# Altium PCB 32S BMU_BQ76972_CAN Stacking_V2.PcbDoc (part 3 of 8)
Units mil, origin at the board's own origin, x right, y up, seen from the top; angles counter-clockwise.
Board outline 7319.29 x 5216.54 mil, 4 copper layers (Top Layer, Layer 1, Layer 2, Bottom Layer), stack 73.068 mil thick; 811 components, 524 nets, 2320 pads, 2669 vias.
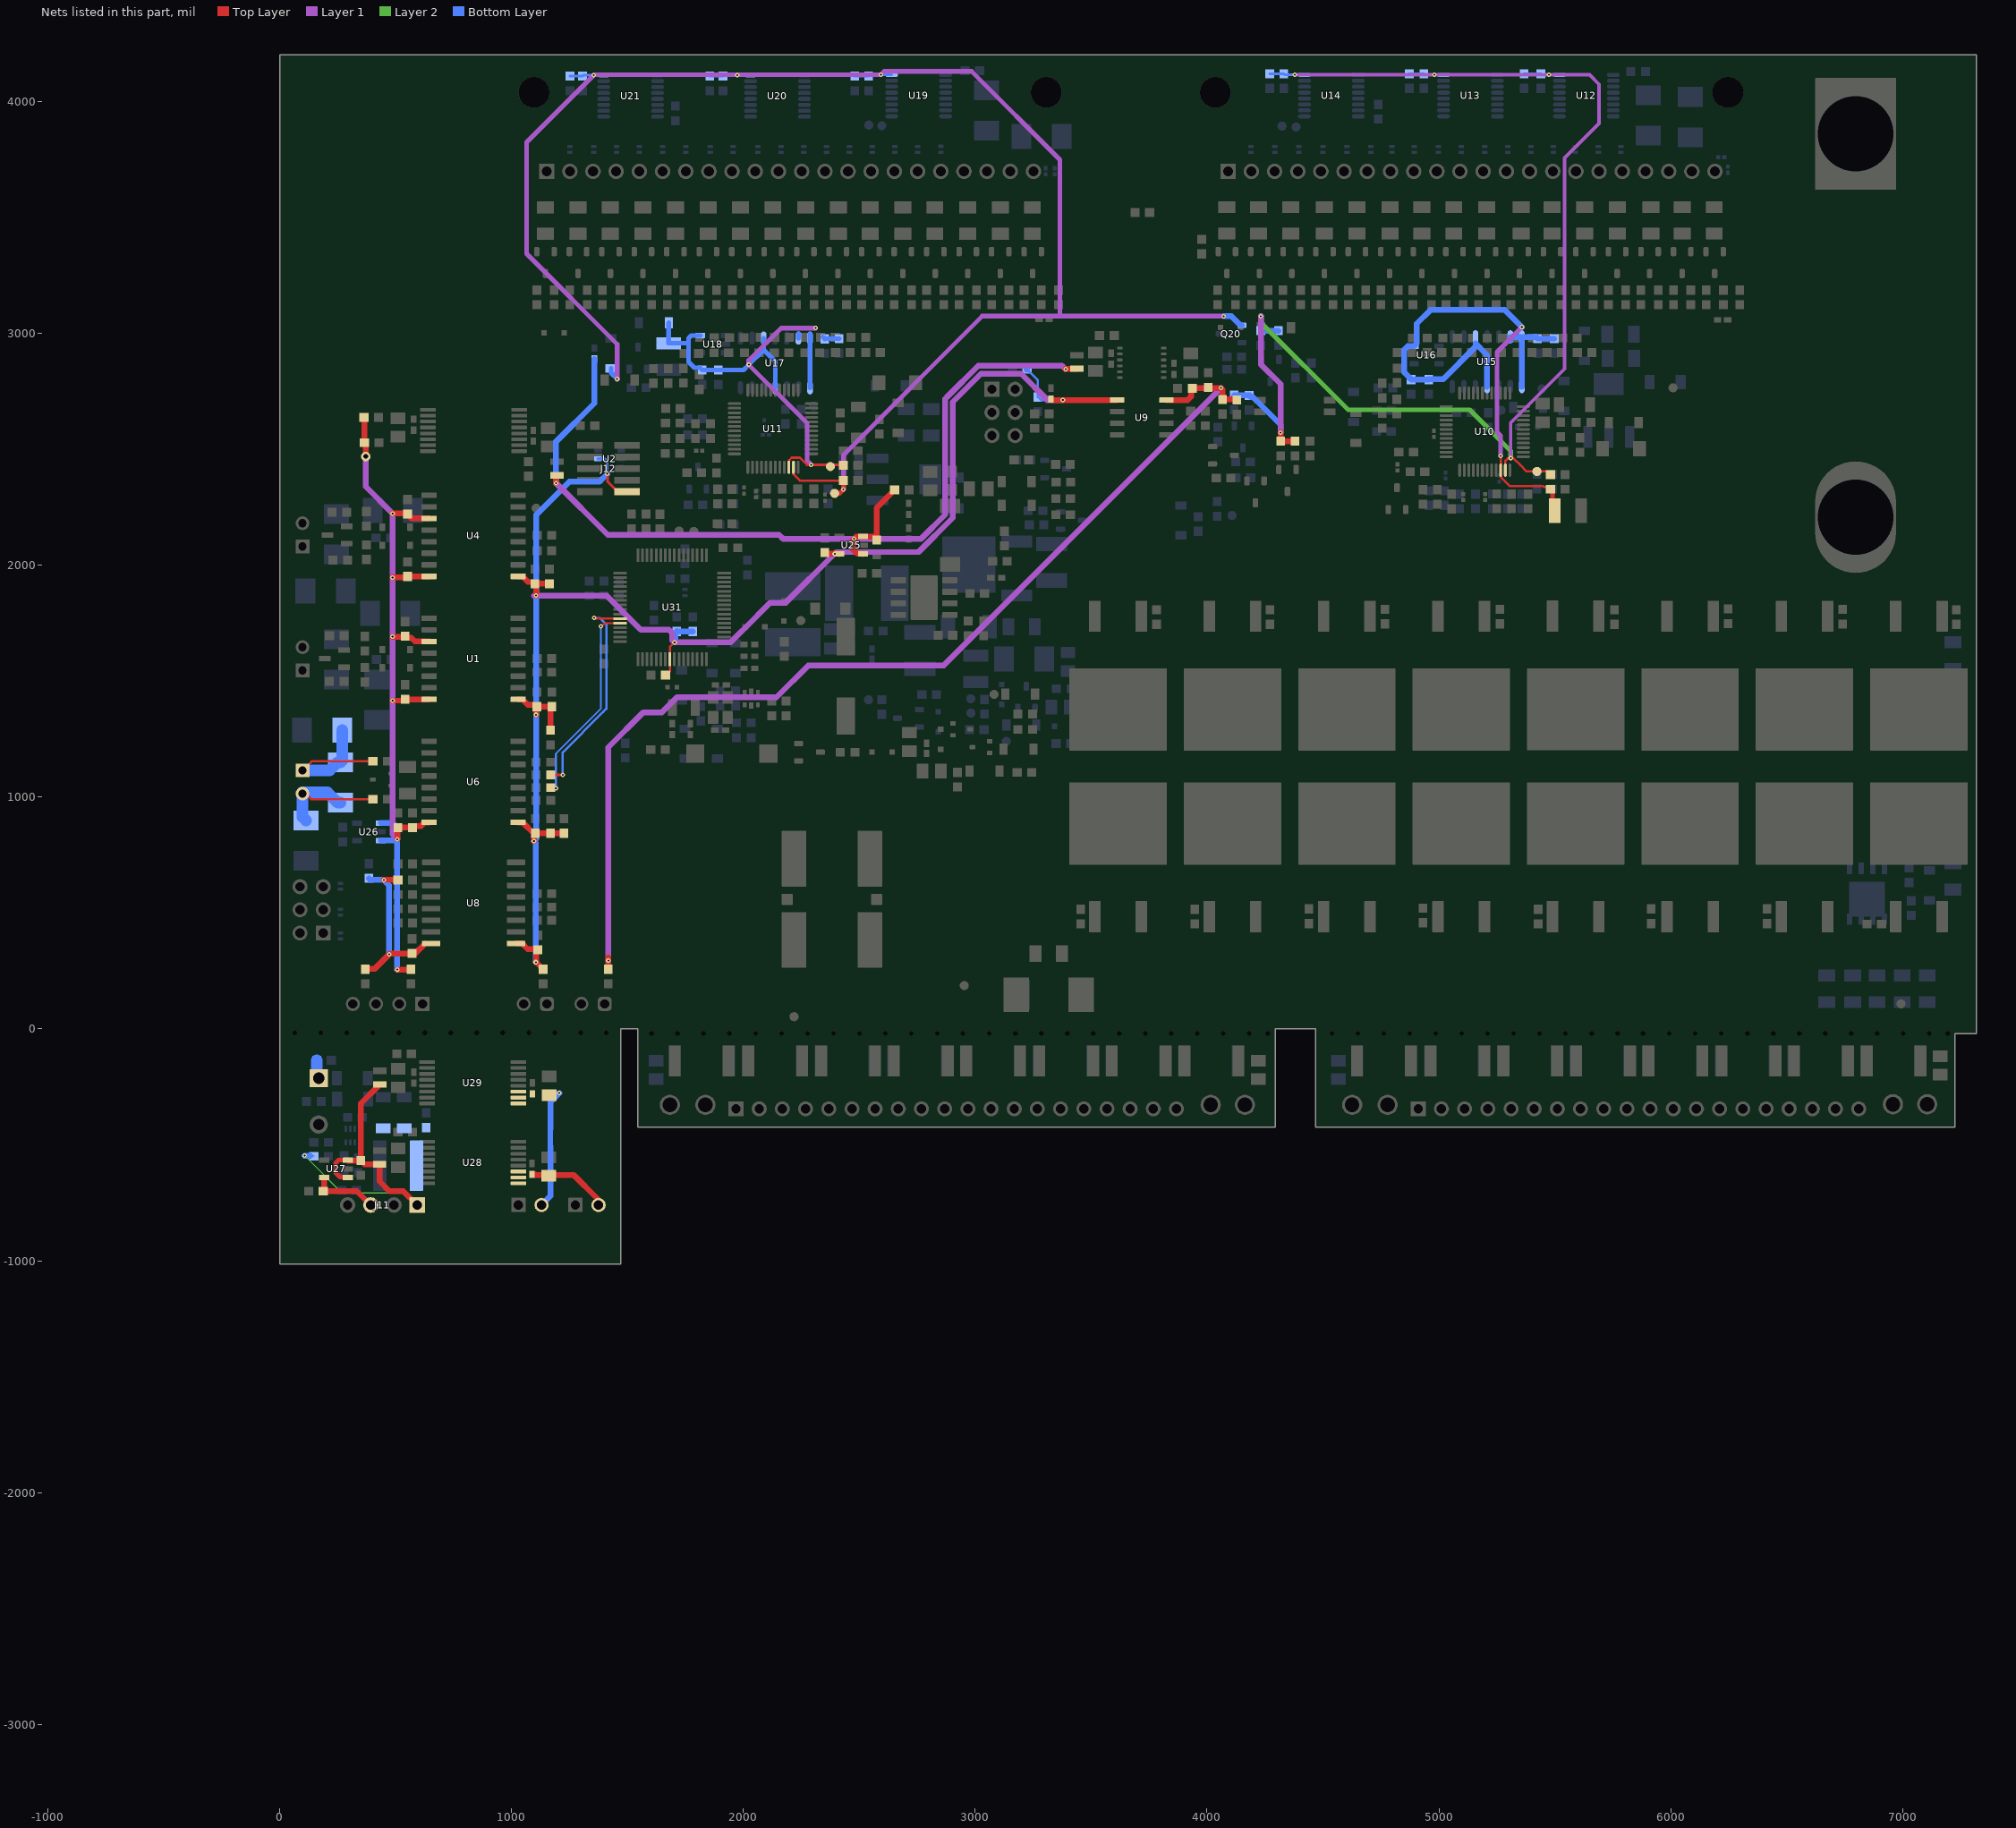
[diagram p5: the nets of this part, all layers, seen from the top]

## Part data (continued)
D38: library part CMP-0005625-1, "Diode, Zener, 91 V, 5 W, SMB", Manufacturer="Micro Commercial Components", PartNumber=SMBJ5375B-TP, Power_W=5W, Supplier Part Number 1=SMBJ5375B-TPMSTR-ND
D39: library part CMP-0076979-3, "Diode, Switching, 100 V, 0.25 A, SOD-523", Manufacturer=Nexperia, Value1=0.25A, Value2=1.25V
D40 D41: library part CMP-0080707-2, "Diode, Schottky, 20 V, 0.5 A, SOD-123", Manufacturer="Diodes Inc.", Value1=0.5A, Value2=0.33V
D43 D44 D45 D46: library part CMP-0006055-3, "Diode, TVS, Bi, 60V， SMB", Manufacturer=Bourns, Value1=600W
D48: library part CMP-0001373-1, "Diode, TVS, Bi, 120 V，3000 W,SMD (non-polarized)", Breakdown Voltage=60V, Clamping Voltage=87.1V, Digikey Part Number=SMDJ54CACT-ND, Manufacturer="Littelfuse Inc", Mouser Part Number=576-SMDJ54CA, Operating Temperature Range="-65°C to +150°C"
D49 D50 D51 D52 D53 D54 D55 D56 D57: library part CMP-0005601-2, "Diode, TVS, Bi, 7 V, SMB", Manufacturer=Littelfuse, Value1=600W
F1: library part CMP-0122193-1, "Fuse Power 150A 240V Bolt Flat 56 X 17.4 X 19.1mm", Digikey Part Number=118-PF-MB1-150-ND, Fuse Current=150A, Fuse Interrupt Dc Current=50000A, Manufacturer=Bourns, Mouser Part Number=652-PF-MB1-150, Operating Temperature Range="-55°C to +125°C"
J1 J2: library part CMP-0087165-1, "Connector Header Through Hole, Right Angle 22 position 0.100\" (2.54mm)", Current_A=3A, Manufacturer=Molex, Voltage_V=250V
J3 J4: library part CMP-0075406-2, "Header, 100mil, 3x2, Gold, TH", Color=Black, Current_A=6.3A, Manufacturer=Samtec, Supplier Part Number 1=SAM1028-03-ND, Voltage_V=550V
J5: library part CMP-0074910-1, "Terminal Block, 5.08 mm, 2x1, Brass, TH", Color=Blue, Current_A=15A, Manufacturer="On-Shore Technology", Supplier Part Number 1=ED1609-ND, Voltage_V=300V
J6 J7: library part CMP-0077643-1, "Header, 2.54mm, 2x1, Gold, TH", Color=Black, Current_A=5.7A, Manufacturer=Samtec, Supplier Part Number 1=SAM1038-02-ND, Voltage_V=550V
J8: library part CMP-0054583-1, "Header, 2.54 mm, 4x1, Gold, TH", Color=Black, Current_A=3A, Manufacturer="Sullins Connector Solutions", Supplier Part Number 1=S1011E-04-ND, Voltage_V=1.8kV
J9 J10: library part CMP-0122186-1, "2 Position Header Connector 0.100\" (2.54mm) Through Hole, Right Angle Tin", Current_A=3A, Digikey Part Number=S5438-ND, Manufacturer=Sullins, Operating Temperature Range="-40°C to +105°C", Voltage_V=250V
J11: library part CMP-0054639-1, "Receptacle, 100mil, 4x1, Gold, R/A, TH", Manufacturer="Sullins Connector Solutions", Supplier Part Number 1=S5479-ND
J12: library part CMP-0075634-1, "Header(Shrouded), 1.27mm, 5x2, Gold, SMT", Color=Black, Current_A=3.3A, Manufacturer=Samtec, Supplier Part Number 1=SAM8799-ND
J14 J15: library part CMP-0075434-1, "Header, 100mil, 20x1, Gold, TH", Color=Black, Current_A=6.3A, Manufacturer="Wurth Elektronik", Supplier Part Number 1=SAM1029-20-ND, Voltage_V=550V
L1: library part CMP-0064154-1, "Inductor, Shielded, 1 uH, 2.7 A, 0.039 ohm, SMD", Manufacturer="Wurth Elektronik", Supplier Part Number 1=732-4863-1-ND, Value1="0.039 ohm", Value2=2.7A, ValueDisplayed=1uH
L2 L5: library part CMP-0122125-1, "51 µH @ 100 kHz 2 Line Common Mode Choke Surface Mount 2.6 kOhms @ 10 MHz 200mA DCR 700mOhm", Digikey Part Number=118-SRF3225TAC-510YCT-ND, Impedance At Frequency="2600Ω @ 10MHz", Manufacturer=Bourns, Mouser Part Number=652-SRF3225TAC-510Y, Operating Temperature Range="-55°C to +150°C", Test Frequency=100kHz, Tolerance_%=-30/+50%
L3 L4 L6 L7 L8 L9: library part CMP-0003196-2, "Ferrite Bead, 600 ohm @ 100 MHz, 0.2 A, 0603", Manufacturer="Wurth Elektronik", Supplier Part Number 1=732-1583-1-ND, Value1="0.45 ohm", Value2=0.2A, ValueDisplayed="600 ohm"
L10: library part CMP-0064631-1, "Inductor, Shielded Drum Core, Metal Composite, 68 uH, 0.87 A, 0.239 ohm, SMD", Manufacturer="Wurth Elektronik", Supplier Part Number 1=732-1201-1-ND, Value1="0.239 ohm", Value2=0.87A, ValueDisplayed=68uH
L11: library part CMP-0064174-2, "Inductor, Shielded, Hyperflux, 10 µH, 5 A, 0.02915 ohm, SMD", Manufacturer="Wurth Elektronik", Supplier Part Number 1=732-10707-1-ND, Value1="0.02915 ohm", Value2=5A, ValueDisplayed=10uH
L12 L13 L14 L15: library part CMP-0100941-1, "WE-PMCI SMT Power Molded Chip Inductor, size 0805, 2.2uH, 2.1A, 190mOhm", Case/Size Code=0805, DC Resistance=180mOhm, DC Resistance Max=190mOhm, Inductance=2.2uH, Manufacturer="Wurth Elektronik", Operating Temperature Max=125°C, Operating Temperature Min=-40°C, Rated Current=2.1A, Saturation Current=2.4A, Self Resonant Frequency=45MHz
LED1: library part CMP-0074720-1, "LED, RGB, SMD", Color=RGB, Manufacturer=Everlight, Supplier Part Number 1=19-337/R6GHBHC-A01/2T-ND, Value1=W, Value2=3.8V
Logo3: library part CMP-0074847-1, "FCC_disclaimer"
Logo4: library part CMP-0074835-1, "IEC 61010-1 High Voltage Warning"
Logo5: library part CMP-0074844-1
Logo6: library part CMP-0074769-1
P1 P2 P3: "Header, 2-Pin"
Q1 Q2 Q3 Q4 Q7 Q8 Q10 Q11 Q12 Q13 Q14 Q15 Q17 Q18 Q21 Q22 Q24 Q25 Q26 Q27 Q28 Q29 Q30 Q31 Q32 Q33 Q36 Q37 Q39 Q40 Q41 Q43: library part CMP-0000433-1, "Transistor, NPN, 40 V, 0.8 A, SOT-23", Manufacturer="NXP Semiconductor", Supplier Part Number 1=568-6225-1-ND, Value1="0.8 A", Value2=300
Q5 Q6 Q16 Q19 Q66: library part CMP-0000338-1, "Transistor, PNP, 80 V, 0.5 A, SOT-23", Manufacturer="ON Semiconductor", Supplier Part Number 1=MMBTA56LT1GOSDKR-ND, Value1="0.5 A"
Q9 Q20 Q23: library part CMP-0000488-1, "Transistor, NPN, 60 V, 0.5 A, AEC-Q101, SOT-23", Manufacturer="ON Semiconductor", Supplier Part Number 1=MMBTA05LT1GOSCT-ND, Value1="0.5 A"
Q34 Q35: library part CMP-0000473-2, "Transistor, NPN, 100 V, 1 A, AEC-Q101, SOT-223", Manufacturer="Diodes Inc.", Supplier Part Number 1=FZT493CT-ND, Value1="1 A", Value2=300
Q38 Q42: library part CMP-0000487-2, "Transistor, NPN, 65 V, 0.1 A, SOT-23", Manufacturer="NXP Semiconductor", Supplier Part Number 1=568-1632-1-ND, Value1="0.1 A", Value2=450
Q44: library part CMP-0000776-1, "MOSFET, N-CH, 60 V, 0.115 A, SOT-323", Alternate Manufacturer=None, Manufacturer="Diodes Inc.", Supplier Part Number 1=2N7002W-FDICT-ND, Value1=7
Q45 Q46 Q47 Q48 Q49 Q50 Q51 Q52 Q56 Q57 Q58 Q59 Q60 Q61 Q62 Q63: library part CMP-0001086-1, "MOSFET, N-CH, 200 V, 134A, DDPAK", Alternate Manufacturer=None, Manufacturer="Infineon Technologies", Value2="70 nC"
Q53: library part CMP-0000116-2, "MOSFET, P-CH, -150 V, -3 A, PowerPAK SO-8", Alternate Manufacturer=None, Manufacturer=Vishay-Siliconix, Supplier Part Number 1=SI7439DP-T1-E3CT-ND, Value2="88 nC"
Q54: library part CMP-0000035-3, "MOSFET, P-CH, -20 V, -0.82 A, SOT-323", Alternate Manufacturer=None, Manufacturer="Diodes Inc.", Value1=0.7, Value2="0.622 nC"
Q55: library part CMP-0074710-1, "Transistor, NPN, 150 V, 1 A, AEC-Q101, SOT-23", Manufacturer="Diodes Inc.", Supplier Part Number 1=FMMT495CT-ND, Value1="1 A", Value2=300.0
Q64: library part CMP-0000093-2, "MOSFET, P-CH, -150 V, -0.53 A, SOT-23", Alternate Manufacturer=None, Manufacturer=Vishay-Siliconix, Supplier Part Number 1=SI2325DS-T1-E3CT-ND, Value2="7.7 nC"
Q65: library part CMP-0000947-2, "MOSFET, N-CH, 100 V, 0.17 A, SOT-23", Alternate Manufacturer=None, Manufacturer="Fairchild Semiconductor", Supplier Part Number 1=BSS123NCT-ND, Value1=1, Value2="1.8 nC"
Q67: library part CMP-0000504-2, "Transistor, NPN, 150 V, 1 A, AEC-Q101, DPAK", Manufacturer="Diodes Inc.", Supplier Part Number 1=ZXTN4004KTCDICT-ND, Value1="1 A"
Q68: library part CMP-0000488-2, "Transistor, NPN, 60 V, 0.5 A, AEC-Q101, SOT-23", Manufacturer="ON Semiconductor", Supplier Part Number 1=MMBTA05LT1GOSCT-ND, Value1="0.5 A"
R1 R48 R49: library part CMP-0025885-5, "RES, 0, 5%, 0.1 W, 0603", Manufacturer=Yageo, Power_W=100mW, Supplier Part Number 1=311-0.0GRCT-ND, TempCo="200 ppm/C", Tolerance_%=5%, Value2=0.1W, Value_Code=0000, ValueDisplayed=NC
R2 R152 R153: library part CMP-0025697-4, "RES, 0, 5%, 0.1 W, AEC-Q200 Grade 0, 0603", Manufacturer=Vishay-Dale, Power_W=100mW, Supplier Part Number 1=541-0.0GCT-ND, TempCo="200 ppm/C", Tolerance_%=5%, Value2=0.1W, Value_Code=0000, ValueDisplayed=0
R3: library part CMP-0122174-1, "High-Precision Low-TCR Alloy Current Sensing Resistor 0.3mOhm 1% 25ppm/°C 15W 3951", Manufacturer="C&B ELECTRONICS", Operating Temperature Range="-55°C to +170°C", Power_W=15W, TempCo=25ppm/°C, Tolerance_%=1%
R5 R28 R30 R45 R188 R189 R192 R199 R249 R252 R254 R329: library part CMP-0021998-4, "RES, 10.0 k, 1%, 0.1 W, AEC-Q200 Grade 0, 0603", Manufacturer=Vishay-Dale, Power_W=100mW, Supplier Part Number 1=541-10.0KHCT-ND, TempCo="100 ppm/C", Tolerance_%=1%, Value2=0.1W, Value_Code=10k0, ValueDisplayed=10.0k
R6 R7 R11 R12 R14 R15 R16 R18 R19 R22 R27 R31 R35 R36 R37 R38 R39 R40 R46 R47 R51 R53 R54 R91 R92 R95 R96 R99 R100 R103 R104 R107 R108 R111 R112 R115 R116 R119 R154 R157 R158 R161 R162 R165 R166 R169 R170 R173 R174 R177 R178 R181 R182 R185 R186 R198 R200 R211 R218 R239 R251 R292: library part CMP-0021991-2, "RES, 100, 1%, 0.1 W, 0603", Manufacturer=Vishay-Dale, Power_W=100mW, Supplier Part Number 1=541-100HCT-ND, TempCo="100 ppm/C", Tolerance_%=1%, Value2=0.1W, Value_Code=100R, ValueDisplayed=100
R8: library part CMP-0022438-1, "RES, 47.0 k, 1%, 0.1 W, AEC-Q200 Grade 0, 0603", Manufacturer=Vishay-Dale, Power_W=100mW, Supplier Part Number 1=541-47.0KHCT-ND, TempCo="100 ppm/C", Tolerance_%=1%, Value2=0.1W, Value_Code=47k0, ValueDisplayed=47.0k
R9 R10 R17 R20: library part CMP-0023213-5, "RES, 60.4, 1%, 0.1 W, 0603", Manufacturer=Yageo, Power_W=100mW, Supplier Part Number 1=311-60.4HRCT-ND, TempCo="100 ppm/C", Tolerance_%=1%, Value2=0.1W, Value_Code=60R4, ValueDisplayed=60.4
R13 R191 R193 R195 R197 R202 R204 R206 R208 R210 R212 R215 R217 R263 R264 R265 R266 R267 R273 R295 R296 R298 R301 R315 R318: "RES, 0, 5%, 0.063 W, 0402", Manufacturer=Vishay-Dale, Power_W=0.063, Supplier Part Number 1=541-0.0JCT-ND, TempCo="200 ppm/C", Tolerance_%=5, Value1=5%, Value2=0.063W, Value_Code=0000, ValueDisplayed=0
R21: library part CMP-0088648-1, "Res Thin Film 0402 100K Ohm 0.1% 1/16W ±25ppm/°C Molded SMD SMD Punched Carrier T/R", Digikey Part Number=P100KDCCT-ND, Manufacturer=Panasonic, Mouser Part Number=667-ERA-2AEB104X, Octopart Part Number=aea26725a1f47165, Operating Temperature Range="-55°C to +155°C", Power_W=63mW, TempCo=25ppm/°C, Tolerance_%=0.1%, Voltage=25V
R23: library part CMP-0026878-1, "RES, 220, 5%, 0.063 W, 0402", Manufacturer=Vishay-Dale, Power_W=63mW, Supplier Part Number 1=541-220JCT-ND, TempCo="200 ppm/C", Tolerance_%=5%, Value2=0.063W, Value_Code=220R, ValueDisplayed=220
R24 R25: library part CMP-0026906-1, "RES, 330, 5%, 0.063 W, 0402", Manufacturer=Vishay-Dale, Power_W=63mW, Supplier Part Number 1=541-330JCT-ND, TempCo="200 ppm/C", Tolerance_%=5%, Value2=0.063W, Value_Code=330R, ValueDisplayed=330
R26 R221: library part CMP-0022248-4, "RES, 26.1 k, 1%, 0.1 W, AEC-Q200 Grade 0, 0603", Manufacturer=Vishay-Dale, Power_W=100mW, Supplier Part Number 1=541-26.1KHCT-ND, TempCo="100 ppm/C", Tolerance_%=1%, Value2=0.1W, Value_Code=26k1, ValueDisplayed=26.1k
R29: "RES, 120, 1%, 0.1 W, 0603", Manufacturer="Yageo America", Power_W=0.1, Supplier Part Number 1=311-120HRCT-ND, TempCo="200 ppm/C", Tolerance_%=1, Value1=1%, Value2=0.1W, Value_Code=120R, ValueDisplayed=120
R32: library part CMP-0023653-3, "RES, 10.0 k, 0.1%, 0.1 W, 0603", Manufacturer="Yageo America", Power_W=100mW, TempCo="25 ppm/C", Tolerance_%=0.1%, Value2=0.1W, Value_Code=10k0, ValueDisplayed=10.0k
R33 R230 R231 R242 R243 R324: library part CMP-0022200-2, "RES, 200 k, 1%, 0.1 W, 0603", Manufacturer=Vishay-Dale, Power_W=100mW, Supplier Part Number 1=541-200KHCT-ND, TempCo="100 ppm/C", Tolerance_%=1%, Value2=0.1W, Value_Code=200k
R34 R233: library part CMP-0023037-5, "RES, 33.0 k, 1%, 0.1 W, 0603", Manufacturer=Yageo, Power_W=100mW, Supplier Part Number 1=311-33.0KHRCT-ND, TempCo="100 ppm/C", Tolerance_%=1%, Value2=0.1W, Value_Code=33k0, ValueDisplayed=33.0k
R41 R42 R43 R44: library part CMP-0023153-5, "RES, 4.70 k, 1%, 0.1 W, 0603", Manufacturer=Yageo, Power_W=100mW, Supplier Part Number 1=311-4.70KHRCT-ND, TempCo="100 ppm/C", Tolerance_%=1%, Value2=0.1W, Value_Code=4k70, ValueDisplayed=4.70k
R50 R203: library part CMP-0082952-1, "RES, 220, 1%, 0.5 W, 1210", Manufacturer=Yageo, Power_W=500mW, TempCo="100 ppm/C", Tolerance_%=1%, Value2=0.5W, Value_Code=220R, ValueDisplayed=220
R52: library part CMP-0021998-4, "RES, 10.0 k, 1%, 0.1 W, AEC-Q200 Grade 0, 0603", Manufacturer=Vishay-Dale, Power_W=100mW, Supplier Part Number 1=541-10.0KHCT-ND, TempCo="100 ppm/C", Tolerance_%=1%, Value2=0.1W, Value_Code=10k0, ValueDisplayed=NC
R55 R56 R57 R58 R59 R60 R61 R62 R63 R64 R65 R66 R67 R68 R69 R70 R71 R72 R73 R74 R75 R76 R77 R78 R79 R80 R81 R82 R83 R84 R85 R86 R120 R121 R122 R123 R124 R125 R126 R127 R128 R129 R130 R131 R132 R133 R134 R135 R136 R137 R138 R139 R140 R141 R142 R143 R144 R145 R146 R147 R148 R149 R150 R151: library part CMP-0017186-1, "RES, 80.6, 1%, 0.25 W, 1206", Manufacturer=Vishay-Dale, Power_W=250mW, Supplier Part Number 1=541-80.6FCT-ND, TempCo="100 ppm/C", Tolerance_%=1%, Value2=0.25W, Value_Code=80R6, ValueDisplayed=80.6
R87 R88: library part CMP-0022206-2, "RES, 20.0, 1%, 0.1 W, 0603", Manufacturer=Vishay-Dale, Power_W=100mW, Supplier Part Number 1=541-20.0HCT-ND, TempCo="100 ppm/C", Tolerance_%=1%, Value2=0.1W, Value_Code=20R0, ValueDisplayed=20.0
R89 R90 R93 R94 R97 R98 R101 R102 R105 R106 R109 R110 R113 R114 R117 R118 R155 R156 R159 R160 R163 R164 R167 R168 R171 R172 R175 R176 R179 R180 R183 R184: library part CMP-0025781-3, "RES, 300, 5%, 0.1 W, 0603", Manufacturer=Vishay-Dale, Power_W=100mW, Supplier Part Number 1=541-300GCT-ND, TempCo="200 ppm/C", Tolerance_%=5%, Value2=0.1W, Value_Code=300R, ValueDisplayed=300
R187 R194 R196 R205 R207 R222 R223 R225 R226 R227 R319: "RES, 0, 5%, 0.063 W, 0402", Manufacturer=Vishay-Dale, Power_W=0.063, Supplier Part Number 1=541-0.0JCT-ND, TempCo="200 ppm/C", Tolerance_%=5, Value1=5%, Value2=0.063W, Value_Code=0000, ValueDisplayed=NC
R190: library part CMP-0025909-5, "RES, 2.0 k, 5%, 0.1 W, 0603", Manufacturer=Yageo, Power_W=100mW, Supplier Part Number 1=311-2.0KGRCT-ND, TempCo="100 ppm/C", Tolerance_%=5%, Value2=0.1W, Value_Code=2k00, ValueDisplayed=2.0k
R201 R209: library part CMP-0016642-2, "RES, 154, 1%, 0.25 W, 1206", Manufacturer=Vishay-Dale, Power_W=250mW, Supplier Part Number 1=541-154FCT-ND, TempCo="100 ppm/C", Tolerance_%=1%, Value2=0.25W, Value_Code=154R, ValueDisplayed=154
R213 R214: library part CMP-0017104-3, "RES, 619, 1%, 0.25 W, AEC-Q200 Grade 0, 1206", Manufacturer=Vishay-Dale, Power_W=250mW, Supplier Part Number 1=541-619FCT-ND, TempCo="100 ppm/C", Tolerance_%=1%, Value2=0.25W, Value_Code=619R, ValueDisplayed=619
R216 R235: library part CMP-0022445-3, "RES, 499 k, 1%, 0.1 W, 0603", Manufacturer=Vishay-Dale, Power_W=100mW, Supplier Part Number 1=541-499KHCT-ND, TempCo="100 ppm/C", Tolerance_%=1%, Value2=0.1W, Value_Code=499k
R219: library part CMP-0023004-4, "RES, 2.00 M, 1%, 0.1 W, 0603", Manufacturer=Yageo, Power_W=100mW, Supplier Part Number 1=311-2.00MHRCT-ND, TempCo="100 ppm/C", Tolerance_%=1%, Value2=0.1W, Value_Code=2M00, ValueDisplayed=2.00M
R220 R236 R237: library part CMP-0023013-5, "RES, 300, 1%, 0.1 W, 0603", Manufacturer=Yageo, Power_W=100mW, Supplier Part Number 1=311-300HRCT-ND, TempCo="100 ppm/C", Tolerance_%=1%, Value2=0.1W, Value_Code=300R, ValueDisplayed=300
R224: library part CMP-0026822-3, "RES, 0, 5%, 0.063 W, AEC-Q200 Grade 0, 0402", Manufacturer=Vishay-Dale, Power_W=63mW, Supplier Part Number 1=541-0.0JCT-ND, TempCo="200 ppm/C", Tolerance_%=5%, Value2=0.063W, Value_Code=0000, ValueDisplayed=0
R228 R240 R241: library part CMP-0022616-2, "RES, 80.6 k, 1%, 0.1 W, 0603", Manufacturer=Vishay-Dale, Power_W=100mW, Supplier Part Number 1=541-80.6KHCT-ND, TempCo="100 ppm/C", Tolerance_%=1%, Value2=0.1W, Value_Code=80k6, ValueDisplayed=80.6k
R229 R248 R250 R253 R282 R294 R297 R303 R304: library part CMP-0025702-4, "RES, 10 M, 5%, 0.1 W, AEC-Q200 Grade 0, 0603", Manufacturer=Vishay-Dale, Power_W=100mW, Supplier Part Number 1=541-10MGCT-ND, TempCo="200 ppm/C", Tolerance_%=5%, Value2=0.1W, Value_Code=10M0, ValueDisplayed=10M
R232 R234 R244 R245 R246 R247: library part CMP-0022060-3, "RES, 150 k, 1%, 0.1 W, 0603", Manufacturer=Vishay-Dale, Power_W=100mW, Supplier Part Number 1=541-150KHCT-ND, TempCo="100 ppm/C", Tolerance_%=1%, Value2=0.1W, Value_Code=150k
R238 R330: library part CMP-0023840-3, "RES, 18.0 k, 0.1%, 0.1 W, 0603", Manufacturer="Yageo America", Power_W=100mW, TempCo="25 ppm/C", Tolerance_%=0.1%, Value2=0.1W, Value_Code=18k0, ValueDisplayed=18.0k
R255: library part CMP-0020477-3, "RES, 1.5 k, 5%, 0.125 W, AEC-Q200 Grade 0, 0805", Manufacturer=Vishay-Dale, Power_W=125mW, Supplier Part Number 1=541-1.5KACT-ND, TempCo="200 ppm/C", Tolerance_%=5%, Value2=0.125W, Value_Code=1k50, ValueDisplayed=1.5k
R256: library part CMP-0025736-3, "RES, 1.0 M, 5%, 0.1 W, 0603", Manufacturer=Vishay-Dale, Power_W=100mW, Supplier Part Number 1=541-1.0MGCT-ND, TempCo="200 ppm/C", Tolerance_%=5%, Value2=0.1W, Value_Code=1M00, ValueDisplayed=1.0M
R257 R260: library part CMP-0022731-2, "RES, 1.00 M, 1%, 0.125 W, 0603", Manufacturer=Vishay/Beyschlag, Power_W=125mW, Supplier Part Number 1=MCT0603-1.00M-CFCT-ND, TempCo="50 ppm/C", Tolerance_%=1%, Value2=0.125W, Value_Code=1M00, ValueDisplayed=1.00M
R258: library part CMP-0024283-1, "RES, 49.9 k, 0.1%, 0.1 W, 0603", Manufacturer="Yageo America", Power_W=100mW, TempCo="25 ppm/C", Tolerance_%=0.1%, Value2=0.1W, Value_Code=49k9, ValueDisplayed=49.9k
R259: library part CMP-0023141-5, "RES, 499, 1%, 0.1 W, 0603", Manufacturer=Yageo, Power_W=100mW, Supplier Part Number 1=311-499HRCT-ND, TempCo="100 ppm/C", Tolerance_%=1%, Value2=0.1W, Value_Code=499R, ValueDisplayed=499
R261 R271: library part CMP-0022615-1, "RES, 806, 1%, 0.1 W, 0603", Manufacturer=Vishay-Dale, Power_W=100mW, Supplier Part Number 1=541-806HCT-ND, TempCo="100 ppm/C", Tolerance_%=1%, Value2=0.1W, Value_Code=806R, ValueDisplayed=806
R262: library part CMP-0023163-5, "RES, 510, 1%, 0.1 W, 0603", Manufacturer=Yageo, Power_W=100mW, Supplier Part Number 1=311-510HRCT-ND, TempCo="100 ppm/C", Tolerance_%=1%, Value2=0.1W, Value_Code=510R, ValueDisplayed=510
R268 R269 R270 R276 R279 R280 R287 R288 R289 R290 R291 R312 R313 R314 R316 R321: library part CMP-0022590-3, "RES, 75.0, 1%, 0.1 W, 0603", Manufacturer=Vishay-Dale, Power_W=100mW, Supplier Part Number 1=541-75.0HCT-ND, TempCo="100 ppm/C", Tolerance_%=1%, Value2=0.1W, Value_Code=75R0, ValueDisplayed=75.0
R272 R283: library part CMP-0020570-1, "RES, 56 k, 5%, 0.125 W, 0805", Manufacturer=Vishay-Dale, Power_W=125mW, Supplier Part Number 1=541-56KACT-ND, TempCo="200 ppm/C", Tolerance_%=5%, Value2=0.125W, Value_Code=56k0, ValueDisplayed=56k
R274 R347 R348 R365 R366: library part CMP-0020847-1, "RES, 10.0, 1%, 0.125 W, 0805", Manufacturer=Vishay-Dale, Power_W=125mW, Supplier Part Number 1=541-10.0CCT-ND, TempCo="100 ppm/C", Tolerance_%=1%, Value2=0.125W, Value_Code=10R0, ValueDisplayed=10.0
R275: library part CMP-0022615-1, "RES, 806, 1%, 0.1 W, 0603", Manufacturer=Vishay-Dale, Power_W=100mW, Supplier Part Number 1=541-806HCT-ND, TempCo="100 ppm/C", Tolerance_%=1%, Value2=0.1W, Value_Code=806R, ValueDisplayed=NC
R277 R278 R284 R285 R286: library part CMP-0017051-2, "RES, 511, 1%, 0.25 W, 1206", Manufacturer=Vishay-Dale, Power_W=250mW, Supplier Part Number 1=541-511FCT-ND, TempCo="100 ppm/C", Tolerance_%=1%, Value2=0.25W, Value_Code=511R, ValueDisplayed=511
R281: library part CMP-0025702-4, "RES, 10 M, 5%, 0.1 W, AEC-Q200 Grade 0, 0603", Manufacturer=Vishay-Dale, Power_W=100mW, Supplier Part Number 1=541-10MGCT-ND, TempCo="200 ppm/C", Tolerance_%=5%, Value2=0.1W, Value_Code=10M0, ValueDisplayed=NC
R293: library part CMP-0022908-4, "RES, 20.0, 1%, 0.1 W, 0603", Manufacturer=Yageo, Power_W=100mW, Supplier Part Number 1=311-20.0HRCT-ND, TempCo="100 ppm/C", Tolerance_%=1%, Value2=0.1W, Value_Code=20R0, ValueDisplayed=20.0
R299 R306 R307: library part CMP-0025830-2, "RES, 5.1 k, 5%, 0.1 W, 0603", Manufacturer=Vishay-Dale, Power_W=100mW, Supplier Part Number 1=541-5.1KGCT-ND, TempCo="200 ppm/C", Tolerance_%=5%, Value2=0.1W, Value_Code=5k10, ValueDisplayed=5.1k
R300: library part CMP-0023210-4, "RES, 604 k, 1%, 0.1 W, 0603", Manufacturer=Yageo, Power_W=100mW, Supplier Part Number 1=311-604KHRCT-ND, TempCo="100 ppm/C", Tolerance_%=1%, Value2=0.1W, Value_Code=604k
R302: library part CMP-0023218-4, "RES, 620 k, 1%, 0.1 W, 0603", Manufacturer=Yageo, Power_W=100mW, Supplier Part Number 1=311-620KHRCT-ND, TempCo="100 ppm/C", Tolerance_%=1%, Value2=0.1W, Value_Code=620k
R308: library part CMP-0078952-1, "RES, 200, 1%, 2 W, 2512", Manufacturer=Bourns, Power_W=2W, Supplier Part Number 1=CRM2512-FX-2000ELF-ND, TempCo="100 ppm/C", Tolerance_%=1%, Value_Code=200R, ValueDisplayed=200
R309: library part CMP-0018065-2, "RES, 20.0 k, 1%, 0.25 W, 1206", Manufacturer="Yageo America", Power_W=250mW, Supplier Part Number 1=311-20.0KFRCT-ND, TempCo="100 ppm/C", Tolerance_%=1%, Value2=0.25W, Value_Code=20k0, ValueDisplayed=20.0k
R310 R311 R322 R323: library part CMP-0022097-1, "RES, 18.2 k, 1%, 0.1 W, 0603", Manufacturer=Vishay-Dale, Power_W=100mW, Supplier Part Number 1=541-18.2KHCT-ND, TempCo="100 ppm/C", Tolerance_%=1%, Value2=0.1W, Value_Code=18k2, ValueDisplayed=18.2k
R317: library part CMP-0023140-4, "RES, 499 k, 1%, 0.1 W, 0603", Manufacturer=Yageo, Power_W=100mW, Supplier Part Number 1=311-499KHRCT-ND, TempCo="100 ppm/C", Tolerance_%=1%, Value2=0.1W, Value_Code=499k, ValueDisplayed=NC
R320: library part CMP-0026439-2, "RES, 523 k, 1%, 0.063 W, AEC-Q200 Grade 0, 0402", Manufacturer=Vishay-Dale, Power_W=63mW, Supplier Part Number 1=541-523KLCT-ND, TempCo="100 ppm/C", Tolerance_%=1%, Value2=0.063W, Value_Code=523k
R325: library part CMP-0022620-1, "RES, 82.5 k, 1%, 0.1 W, 0603", Manufacturer=Vishay-Dale, Power_W=100mW, Supplier Part Number 1=541-82.5KHCT-ND, TempCo="100 ppm/C", Tolerance_%=1%, Value2=0.1W, Value_Code=82k5, ValueDisplayed=82.5k
R326: library part CMP-0022743-5, "RES, 10.2 k, 1%, 0.1 W, 0603", Manufacturer=Yageo, Power_W=100mW, Supplier Part Number 1=311-10.2KHRCT-ND, TempCo="100 ppm/C", Tolerance_%=1%, Value2=0.1W, Value_Code=10k2, ValueDisplayed=10.2k
R327: library part CMP-0023176-5, "RES, 53.6 k, 1%, 0.1 W, 0603", Manufacturer=Yageo, Power_W=100mW, Supplier Part Number 1=311-53.6KHRCT-ND, TempCo="100 ppm/C", Tolerance_%=1%, Value2=0.1W, Value_Code=53k6, ValueDisplayed=53.6k
R328: library part CMP-0022540-4, "RES, 63.4 k, 1%, 0.1 W, AEC-Q200 Grade 0, 0603", Manufacturer=Vishay-Dale, Power_W=100mW, Supplier Part Number 1=541-63.4KHCT-ND, TempCo="100 ppm/C", Tolerance_%=1%, Value2=0.1W, Value_Code=63k4, ValueDisplayed=63.4k
R331 R332 R333 R334 R335 R336 R337 R338 R339 R340 R341 R342 R343 R344 R345 R346 R349 R350 R351 R352 R353 R354 R355 R356 R357 R358 R359 R360 R361 R362 R363 R364: library part CMP-0015526-3, "RES, 200, 1%, 1 W, AEC-Q200 Grade 0, 2512", Manufacturer=Vishay-Dale, Power_W=1W, Supplier Part Number 1=541-200AFCT-ND, TempCo="100 ppm/C", Tolerance_%=1%, Value_Code=200R, ValueDisplayed=200
RT1 RT3 RT4 RT5 RT6 RT7 RT8 RT9 RT10 RT11 RT12 RT13 RT14 RT15 RT16 RT17 RT18 RT19 RT21 RT22 RT23 RT24 RT25 RT26 RT27 RT28 RT29 RT30 RT31 RT32 RT33 RT34 RT35 RT36 RT37: library part CMP-0084566-1, "Thermistor, DEC0002A (X1SON-2)", Alternate Manufacturer="Texas Instruments", Alternate PartNumber=TMP6131DECT
S1: library part CMP-0002210-1, "Switch, Tactile, SPST-NO, 0.05A, 12V, SMD", CurrentRating_mA=50A, Manufacturer="C&K Components", Supplier Part Number 1=CKN10388CT-ND
S2: library part CMP-0002221-2, "Switch, SPST, Off-On, 2 Pos, SMD", CurrentRating_mA=25A, Manufacturer="Wurth Elektronik", Supplier Part Number 1=732-3852-1-ND
TP9 TP12 TP25 TP27: library part CMP-0055146-2, "Test Point, Compact, Yellow, TH", Color=Yellow, Manufacturer="Keystone Electronics", PartNumber=5009, Supplier Part Number 1=36-5009-ND
TP17 TP28: library part CMP-0055148-1, "Test Point, Multipurpose, Black, TH", Color=Black, Manufacturer=Keystone, PartNumber=5011, Supplier Part Number 1=36-5011-ND
TP24 TP29: library part CMP-0055147-1, "Test Point, Multipurpose, Red, TH", Color=Red, Manufacturer=Keystone, PartNumber=5010, Supplier Part Number 1=36-5010-ND
U1 U4: library part CMP-0078146-3, "Isolated CAN Transceiver With 70-V Bus Fault Protection and Flexible Data Rate, DW0016B (SOIC-16)", Alternate Manufacturer="Texas Instruments", Operating Temperature Range="-40 to 125 C", Rating=Catalog
U2: library part CMP-0043108-1, "Low-Capacitance + / - 15-kV ESD Protection Array for High-Speed Data Interfaces, 4 Channels, -40 to +85 degC, 6-pin SOT-23 (DBV), Green (RoHS & no Sb/Br)", Breakdown Voltage(Min)(V)=11, IO Capacitance(Typ)(pF)=1.5, Manufacturer="Texas Instruments"
U3 U5: library part CMP-0093261-1, "24-V, 2-Channel ESD Protection Diode for In-Vehicle Networks", Breakdown Voltage=25.5V, Clamping Voltage=32V, Manufacturer="Texas Instruments", Operating Temperature Range="-55°C to +150°C", PartNumber=ESD2CANFD24DBZR, ValueDisplayed=3pF
U6: library part CMP-0081937-2, "5-kVRMS Reinforced and Basic Isolated RS-485/RS-422 Transceiver With Robust-EMC, DW0016B (SOIC-16)", Alternate Manufacturer="Texas Instruments", Alternate PartNumber=ISO1410DW, Operating Temperature Range="-40 to 125 C"
U7: library part CMP-0043100-2, "ESD Protection Array for AC Signal Data Interface, 2 Channels, -40 to +85 degC, 3-pin SC70 (DCK), Green (RoHS & no Sb/Br)", Breakdown Voltage(Min)(V)=+/-14, IO Capacitance(Typ)(pF)=15, IO Leakage Current(nA)=50, Manufacturer="Texas Instruments"
U8: library part CMP-0094636-1, Digikey Part Number=296-ISO6731DWRCT-ND, Manufacturer="Texas Instruments", Max Supply Voltage=5.5V, Min Supply Voltage=1.71V, Mouser Part Number=595-ISO6731DWR, Operating Temperature Range="-40°C to +125°C"
U9: library part CMP-0091761-1, Digikey Part Number=296-ISO1640BDRCT-ND, Manufacturer="Texas Instruments", Max Supply Voltage=5.5V, Min Supply Voltage=2.25V, Mouser Part Number=595-ISO1640BDR, Nominal Supply Current=2.7-5.3mA, Operating Temperature Range="-40°C to +125°C"
U10 U11: library part CMP-0084230-1, "Multicell Battery Monitor and Protection Family, PFB0048A (TQFP-48)", Alternate Manufacturer="Texas Instruments", Alternate PartNumber=bq76952PFBT, PartNumber=bq76972PFBR
U12 U13 U14 U19 U20 U21: library part CMP-0066257-1, "Catalog Dual 4-Channel Analog Multiplexer/Demultiplexer, PW0016A (TSSOP-16)", Alternate Manufacturer="Texas Instruments"
U15 U17: library part CMP-0049499-1, "Schmitt-trigger input dual D-type positive-edge-triggered flip-flops w/ clear and preset", F @ Nom Voltage(Max)(Mhz)=100, ICC @ Nom Voltage(Max)(mA)=0.01, Manufacturer="Texas Instruments", Operating Temperature Range(C)="-40 to 125", Rating=Catalog, tpd @ Nom Voltage(Max)(ns)=7.1,4.4,6,5.2, Voltage(Nom)(V)=1.8,2.5,2.7,3.3
U16 U18: library part CMP-0052043-2, "Single 2-Input Exclusive-OR Gate, DBV0005A (SOT-23-5)", F @ Nom Voltage(Max)(Mhz)=250, Generic Part Number=SN74AUC1G86, ICC @ Nom Voltage(Max)(mA)=0.01, Manufacturer="Texas Instruments", Operating Temperature Range="-40 to 85 C", Rating=Catalog, tpd @ Nom Voltage(Max)(ns)=5.5,3.8,2.6,1.7,1.3, Voltage(Nom)(V)=0.8,1.2,1.5,1.8,2.5
U22: library part CMP-0098322-4, "1.5W, High-Density, >3 kVRMS Isolated DC-DC Converter", Manufacturer="Texas Instruments", Max Supply Voltage=5.5V, Min Supply Voltage=4.5V, Operating Temperature Range=to, Output Voltage=5V, Part Number=UCC33420
U23: library part CMP-0120108-2, "1.5W, High-Density, >5 kVRMS Isolated DC-DC Converter", Manufacturer="Texas Instruments", Max Supply Voltage=5.5V, Min Supply Voltage=4.5V, Operating Temperature Range="-40°C to +125°C", Output Voltage=5/5.5V, PartNumber=UCC33421
U24: library part CMP-0861029-1, "0.3-A,120-V, Step-Down Converter with Fly-buck Capability", Alternate Manufacturer="Texas Instruments"
U25 U26 U27: library part CMP-0120272-1, "200-mA, 18-V, ultra-low-IQ, low-dropout (LDO) voltage regulator with enable 5-SOT-23 -40 to 125", Digikey Part Number=296-TPS7A2433DBVRCT-ND, Dropout Voltage=160mV, Manufacturer="Texas Instruments", Max Supply Voltage=18V, Min Supply Voltage=3.8V, Mouser Part Number=595-TPS7A2433DBVR, Nominal Supply Current=2-15uA, Operating Temperature Range="-40°C to +125°C", Output Voltage=3.3V
U28 U29: library part CMP-0120108-2, "1.5W, High-Density, >5 kVRMS Isolated DC-DC Converter", Manufacturer="Texas Instruments", Max Supply Voltage=5.5V, Min Supply Voltage=4.5V, Operating Temperature Range="-40°C to +125°C", Output Voltage=5/5.5V, PartNumber=UCC33411
U30: library part CMP-0094457-2, "3.8-V to 30-V, 2-A Synchronous Buck Converter in SOT583 Package", Manufacturer="Texas Instruments", Max Supply Voltage=30V, Min Supply Voltage=3.8V, Nominal Supply Current=12uA, Operating Temperature Range="-40°C to +150°C", Output Voltage=0.8-22V, Switching Frequency=310-2100kHz
U31: library part CMP-0093960-1, "Mixed-Signal Microcontrollers With CAN-FD Interface LQFP64", Frequency_Fixed=80MHz, Manufacturer="Texas Instruments", Max Supply Voltage=3.6V, Min Supply Voltage=1.62V, Operating Temperature Range="-40°C to +125°C", Part Number=MSPM0G3507SPM
U32 U33 U34: library part CMP-0043093-4, "Single-Channel ESD in 0402 Package With 10pF Capacitance and 6V Breakdown, DPY0002A (X1SON-2)", Alternate Manufacturer="Texas Instruments", Alternate PartNumber=TPD1E10B06DPYT, Breakdown Voltage(Min)(V)=6, IO Capacitance(Typ)(pF)=10, Operating Temperature Range="-40 to 125 C", Rating=Catalog
Y1: library part CMP-0004693-2, "Crystal, 32.768 KHz, 12.5 pF, SMD", Frequency_Fixed=32.768kHz, Manufacturer=Epson
Y2: library part CMP-0098168-2, "Crystal 40MHz ±10ppm (Tol) ±20ppm (Stability) 12pF FUND 40Ohm 4-Pin Mini-CSMD T/R", Frequency Stability=20ppm, Frequency Tolerance=10ppm, Frequency_Fixed=40MHz, Load Capacitance=12pF, Manufacturer="Seiko Epson", Operating Temperature Range="-40°C to +105°C"
ZZ1: library part CMP-0077236-1
ZZ2: library part CMP-0077237-1
ZZ3: library part CMP-0077238-1

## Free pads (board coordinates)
  rect 0x0 hole 20 square unplated mask+1.97: ""(65.54,-16.78) ""(177.6,-16.78) ""(289.65,-16.78) ""(401.7,-16.78) ""(513.76,-16.78) ""(625.81,-16.78) ""(737.86,-16.78) ""(849.91,-16.78) ""(961.97,-16.78) ""(1074.02,-16.78) ""(1186.07,-16.78) ""(1298.13,-16.78) ""(1408.37,-16.78) ""(1604.33,-19.68) ""(1716.38,-19.68) ""(1828.44,-19.68) ""(1940.49,-19.68) ""(2052.54,-19.68) ""(2164.6,-19.68) ""(2276.65,-19.68) ""(2388.7,-19.68) ""(2500.76,-19.68) ""(2612.81,-19.68) ""(2724.86,-19.68) ""(2836.91,-19.68) ""(2947.16,-19.68) ""(3061.02,-19.68) ""(3173.08,-19.68) ""(3285.13,-19.68) ""(3397.18,-19.68) ""(3509.24,-19.68) ""(3621.29,-19.68) ""(3733.34,-19.68) ""(3845.4,-19.68) ""(3957.45,-19.68) ""(4069.5,-19.68) ""(4181.55,-19.68) ""(4261.81,-19.68) ""(4538.13,-19.68) ""(4650.19,-19.68) ""(4762.24,-19.68) ""(4874.29,-19.68) ""(4986.34,-19.68) ""(5098.4,-19.68) ""(5210.45,-19.68) ""(5322.5,-19.68) ""(5434.56,-19.68) ""(5546.61,-19.68) ""(5658.66,-19.68) ""(5770.72,-19.68) ""(5880.96,-19.68) ""(5994.09,-19.68) ""(6106.15,-19.68) ""(6218.2,-19.68) ""(6330.25,-19.68) ""(6442.31,-19.68) ""(6554.36,-19.68) ""(6666.41,-19.68) ""(6778.47,-19.68) ""(6890.52,-19.68) ""(7002.57,-19.68) ""(7114.63,-19.68) ""(7194.88,-19.68)

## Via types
v1: diameter 19.68, hole 7.87, Top Layer to Bottom Layer, tented both sides, 2668 vias
v2: diameter 40, hole 20, Top Layer to Bottom Layer, 1 vias

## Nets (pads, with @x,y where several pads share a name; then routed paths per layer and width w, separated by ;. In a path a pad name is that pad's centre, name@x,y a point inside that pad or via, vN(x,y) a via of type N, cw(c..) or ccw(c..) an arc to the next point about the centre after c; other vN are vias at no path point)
2V5BOT: C81.2 C106.1 C107.1 C108.1 C109.1 D41.2 R203.2 TP23.1 U11.34 U17.1 U17.4 U17.10 U17.13 U17.14 U18.5 | length 2441.4
  Top Layer w10: U11.34@2196.53,2422.69 2196.88,2423.04 2196.88,2452.73 2208.39,2464.23 2243.73,2464.23 2274.43,2433.54 2429.09,2433.54 C81.2@2431.22,2431.41
  Layer 1 w20: v1(2292,2433.54) 2274.73,2450.81 2274.73,2613.47 v1(2023.27,2864.93) 2023.27,2883.76 2162.78,3023.27 v1(2311.11,3023.27)
  Bottom Layer w20: D41.2@1678.48,3046 1678,3045.53 R203.2@1678,2957.71 1762.58,2957.71 1763.89,2956.41 ; C107.1@1813.78,2852.59 1788.76,2852.59 1763.89,2877.47 1763.89,2956.41 ; U18.5@1814.61,2991.57 1775.6,2991.57 1763.89,2979.85 1763.89,2956.41 ; C107.1@1822.48,2842.91 C106.1@1891.89,2842.91 2001.25,2842.91 v1(2023.27,2864.93) 2087.48,2929.13 ; U17.10@2087.48,2980.12 2087.48,2929.13 ; U17.4@2137.48,2765.55 2137.48,2879.13 2087.48,2929.13 ; U17.13@2237.48,2980.12 2237.48,2995.87 U17.13@2239.15,2997.54 ; U17.1@2287.48,2765.55 U17.14@2287.48,2980.12 U17.14@2287.48,2995.87 ; C109.1@2342.73,2985.32 C109.1@2351.43,2976.62 2351.93,2977.11 2412.13,2977.11 C108.1@2412.63,2977.6
2V5TOP: C75.2 C96.1 C97.1 C98.1 C99.1 R50.2 U10.34 U15.1 U15.4 U15.10 U15.13 U15.14 U16.5 | length 2813.3
  Top Layer w10: v1(5266.79,2472.51) 5266.91,2472.39 U10.34@5266.91,2410.2 5266.91,2381.65 5267.69,2380.87 5267.69,2379.73 5306.09,2341.33 5448.48,2341.33 5452.49,2337.33 5472.17,2337.33 C75.2@5481.31,2328.18
  Top Layer w20: C75.2@5481.31,2328.18 C75.2@5481.31,2328.18 5490.07,2319.48 5490.07,2245.47 R50.2@5499.31,2236.23
  Layer 1 w20: v1(5266.79,2472.51) 5266.79,2558.24 5250.19,2574.84 5250.19,2919.88 v1(5357.86,3027.55)
  Bottom Layer w25: C97.1@4956.51,2801.27 C96.1@4880.54,2801.27 4874.34,2807.47 4874.34,2808.45 4850.96,2831.84 4850.96,2930.24 4865.6,2944.88 U16.5@4892.72,2944.88 4904.7,2956.86 4904.7,3041.71 4964.2,3101.21 5284.2,3101.21 v1(5357.86,3027.55) ; C97.1@4956.51,2802.25 5017.93,2802.25 5158.17,2942.49 5158.17,2956.81 5207.86,2907.12 U15.4@5207.86,2770.67 ; U15.13@5307.86,2969.88 U15.13@5307.86,2985.24 U15.14@5357.86,2985.24 ; U15.1@5357.86,2770.67 U15.14@5357.86,2985.24 ; C98.1@5497.53,2977.6 C99.1@5425.95,2977.6 5425.95,2978.59 5419.3,2985.24 U15.14@5357.86,2985.24
3V3: C1.1 C2.1 C3.1 C6.1 C19.2 C59.1 C60.1 C68.1 C136.1 C138.1 C139.1 J12.1 R5.2 R8.2 R43.2 R44.2 R49.1 R192.1 U1.1 U2.5 U4.1 U6.1 U8.1 U9.1 U25.5 U31.40 | length 7579.3
  Top Layer w10: R8.2@1664.39,1526.2 1665.38,1526.2 1682.93,1543.76 U31.40@1682.93,1594.69 1682.93,1647.5 v1(1702.76,1667.32)
  Top Layer w12: v1(1412.81,2394.3) 1414.24,2392.88 1414.24,2360.46 1457.09,2317.61 J12.1@1497.44,2317.61
  Top Layer w25: U8.1@1019.56,368.59 1045.74,368.59 1070.05,344.28 C19.2@1105.8,344.28 ; U6.1@1028.41,891.17 1047.7,891.17 C59.1@1094.53,844.35 ; U1.1@1028.41,1421.63 1047.7,1421.63 1072.02,1397.32 1103.16,1397.32 1109.36,1391.11 C1.1@1109.36,1390.13 ; U4.1@1028.41,1952.08 1047.7,1952.08 1072.02,1927.77 1094.3,1927.77 C3.1@1097.2,1924.87 ; v1(1096.75,810.02) 1096.75,842.12 C59.1@1094.53,844.35 ; v1(1106.07,1355.47) 1106.07,1386.83 C1.1@1109.36,1390.13 ; v1(1106.07,1870.1) 1106.07,1915.02 C3.1@1100.5,1920.58 C6.1@1163.49,1920.58 ; C19.2@1113.26,340.93 1107.06,334.73 1107.06,290.65 v1(1104.67,288.26) 1105.97,288.26 R49.1@1136.57,257.65 ; R192.1@1168.79,1288.58 1168.79,1385 C2.1@1173.92,1390.13 C1.1@1109.36,1390.13 ; R5.2@1226.55,844.35 C60.1@1168.79,844.35 C59.1@1103.16,844.35 C59.1@1094.53,844.35 ; C136.1@2350.74,2055.18 2355.96,2049.96 v1(2393.81,2049.96) 2412.77,2049.96 U25.5@2413.45,2049.28 ; C68.1@3330.53,2712.79 v1(3377.94,2712.79) U9.1@3612.3,2712.79
  Layer 1 w25: v1@1097.2,1869.07 1097.96,1868.31 1411.31,1868.31 1557.19,1722.44 1678.82,1722.44 1693.46,1707.8 1693.46,1676.61 v1(1702.76,1667.32) 1944.46,1667.32 2049.79,1772.65 2049.97,1772.65 2067.74,1790.42 2067.74,1790.6 2115.73,1838.59 2182.44,1838.59 v1(2393.81,2049.96) 2400.93,2057.09 2755.91,2057.09 2903.54,2204.72 2903.54,2704.46 3024.96,2825.88 3198.07,2825.88 3311.16,2712.79 v1(3377.94,2712.79)
  Bottom Layer w10: R43.2@3223.25,2845.89 3270.36,2798.77 R44.2@3270.36,2725.9 3283.48,2712.79 v1(3377.94,2712.79)
  Bottom Layer w12: U2.5@1372.56,2459.36 1401.1,2459.36 1412.81,2447.65 v1(1412.81,2394.3)
  Bottom Layer w25: v1(1104.67,288.26) 1104.67,802.11 v1(1096.75,810.02) 1105.98,819.25 1105.98,1355.39 v1(1106.07,1355.47) v1(1106.07,1870.1) 1106.07,2217.55 1248.82,2360.31 1378.81,2360.31 v1(1412.81,2394.3) ; v1(1702.76,1667.32) 1706.4,1670.96 1706.4,1710.33 1712.6,1716.54 1714.57,1714.57 C138.1@1781.5,1714.57 ; R43.2@3221.63,2844.27 R43.2@3223.25,2845.89
3V3_EXT: C153.1 C155.1 J9.2 U29.9 U29.10 U29.11 | length 515
  Bottom Layer w25: J9.2@1129.42,-759.47 1167.53,-721.35 1167.53,-507.35 1167.29,-507.1 1167.29,-432.28 1167.53,-432.03 1167.53,-315.21 v1(1206.25,-276.49)
3V3_ISO: C20.2 R1.1 R45.2 R266.2 U8.16 | length 754.7
  Top Layer w25: R1.1@368.86,257.65 369.96,258.76 409.18,258.76 476.26,325.84 573.51,325.84 C20.2@575.55,323.8 ; v1(448.7,642.77) R45.2@509.95,642.77 ; C20.2@584.48,325.84 U8.16@626.54,367.9
  Bottom Layer w25: R266.2@384.71,649.66 384.71,648.97 390.91,642.77 v1(448.7,642.77) 471.83,619.64 v1(471.83,321.41)
3V3_ISO_EXT: C11.1 J11.3 U27.5 | length 290.1
  Top Layer w25: U27.5@191.85,-640.91 191.85,-695.27 C11.1@187.79,-699.33 332.75,-699.33 J11.3@392.89,-759.47
3V3_TOP_EXT: C152.1 C154.1 J10.2 U28.9 U28.10 U28.11 | length 351.7
  Top Layer w25: C152.1@1098.5,-625.42 1098.5,-627.98 1099.95,-629.43 1170.26,-629.43 1267.58,-629.43 1368.83,-730.69 1368.83,-731.55 1386.79,-749.51 J10.2@1386.79,-759.47
3V3_TOP_ISO: C63.2 R41.2 R42.2 R48.1 R267.2 U9.8 | length 4635.2
  Top Layer w25: R48.1@1417.32,271.65 v1(1417.32,295.74) 1417.32,309.74 ; U9.8@3824.9,2712.79 3916.28,2712.79 3930.93,2727.43 3930.93,2757.98 R267.2@3936.36,2763.42 C63.2@4010.08,2763.42 ; C63.2@4005.34,2764.54 v1(4060.48,2764.54) 4066.99,2758.03 R42.2@4066.99,2715.49 4125.94,2715.49 R41.2@4128.32,2713.11
  Layer 1 w25: v1(1417.32,295.74) 1417.32,1214.36 1568.95,1365.98 1648.79,1365.98 1713.48,1430.67 2143.27,1430.67 2280.48,1567.88 2863.83,1567.88 v1(4060.48,2764.54)
3V3BOT: C80.2 C100.1 C101.1 C102.1 C103.1 C104.1 C105.1 D40.2 Q20.1 TP25.1@2393.81,2310.15 U11.35 U19.16 U20.16 U21.16 | length 7459.3
  Top Layer w10: U11.35@2216.22,2422.69 2216.57,2422.34 2216.57,2392.66 2228.07,2381.15 2228.25,2381.15 2243.8,2365.6 C80.2@2431.22,2365.6
  Top Layer w20: TP25.1@2393.81,2310.15 2415.14,2310.15 v1(2431.96,2326.97) 2431.96,2364.86 C80.2@2431.22,2365.6
  Layer 1 w20: v1(1455.59,2803.16) 1455.59,2953.17 1064.42,3344.34 1064.42,3824.58 v1(1354.3,4114.46) 1355.87,4116.03 v1(2593.51,4116.03) 2607.93,4130.45 2984.28,4130.45 3365.14,3749.6 3365.14,3074.8 ; v1(2431.96,2326.97) 2431.96,2475.97 3030.8,3074.8 3365.14,3074.8 ; v1(4071.95,3074.8) 3365.14,3074.8
  Bottom Layer w12: C104.1@1252.2,4110.13 C105.1@1306.34,4110.13 1310.39,4114.17 U21.16@1397.64,4114.17 ; C103.1@1855.12,4110.13 C102.1@1912.21,4110.13 1916.26,4114.17 U20.16@2030.84,4114.17 ; C100.1@2479.96,4110.13 C101.1@2540.79,4110.13 2546.41,4115.75 U19.16@2640.03,4115.75
  Bottom Layer w20: D40.2@1429.35,2849.16 1429.35,2829.4 v1(1455.59,2803.16)
  Bottom Layer w25: v1(4071.95,3074.8) 4104.7,3074.8 4144.07,3035.43 Q20.1@4150.57,3035.43
  other v1: 1973.84,4114.46
3V3TOP: C74.2 C90.1 C91.1 C92.1 C93.1 C94.1 C95.1 R220.1 R228.2 R236.1 R237.1 R240.2 R241.2 TP26.1 U10.35 U12.16 U13.16 U14.16 | length 6253.7
  Top Layer w10: U10.35@5286.6,2410.2 5286.94,2410.54 5286.94,2451.16 5296.59,2460.82 v1@5307.87,2460.82 ; v1@5309.84,2462.95 5320.47,2462.95 ; 5320.47,2462.77 5350.63,2432.62 5350.8,2432.62 5378.62,2404.8 5467.61,2404.8 C74.2@5481.31,2391.1
  Top Layer w25: v1(4317.32,2572.83) R220.1@4317.32,2535.43 4379.51,2535.43 R228.2@4379.66,2535.28
  Layer 1 w15: v1(4378.32,4116.03) v1(4980.52,4116.03) 5574.48,4116.03 5650.05,4116.03 5691.28,4074.8 5691.28,3906.45 5542.63,3757.81 5542.63,3719.93 5542.51,3719.81 5542.51,3679.41 5542.63,3679.28 5542.63,2847.42 5309.72,2614.51 v1(5309.72,2462.67)
  Layer 1 w25: v1(4232.16,3074.8) 4232.16,2866.4 4317.32,2781.24 v1(4317.32,2572.83)
  Layer 2 w20: v1(4232.16,3074.8) 4232.16,3047.34 4609.36,2670.15 5132.7,2670.15 5309.72,2493.13 v1(5309.72,2462.67)
  Bottom Layer w12: C95.1@4270.53,4120.27 C94.1@4331.47,4120.27 4336,4115.75 U14.16@4420.07,4115.75 ; C93.1@4872.45,4120.27 C92.1@4935.82,4120.27 4940.35,4115.75 U13.16@5020.12,4115.75 ; C90.1@5367.5,4120.27 C91.1@5440.22,4120.27 5444.75,4115.75 U12.16@5520.17,4115.75
  Bottom Layer w25: R241.2@4117.29,2733.4 R237.1@4185.44,2733.4 ; R237.1@4181.58,2733.04 4181.58,2732.06 4187.78,2725.86 4197.37,2725.86 4220.78,2702.45 4317.32,2605.91 v1(4317.32,2572.83) ; v1(4232.16,3074.8) R240.2@4232.16,3011.98 R236.1@4307.77,3011.98
  other v1: 5474.48,4116.03
5V: C114.1 L14.1 L15.1 R224.2 R264.2 U25.1 U25.3 | length 4048.5
  Top Layer w25: v1(1192.2,2354.32) 1192.2,2384.46 L14.1@1195.82,2388.08 ; U25.1@2515.82,2049.28 2515.13,2049.96 2491.25,2049.96 2473.66,2067.55 2473.66,2110.12 2486.93,2123.39 2515.13,2123.39 U25.3@2515.82,2124.08 2559.79,2124.08 C114.1@2574.66,2109.21 2574.66,2247.74 R264.2@2652.19,2325.27 ; v1(3389.73,2845.89) 3390.34,2846.49 3437.94,2846.49 L15.1@3439.22,2847.77
  Layer 1 w25: v1(1192.2,2354.32) 1415.04,2131.48 2154.17,2131.48 2171.13,2114.51 2766.66,2114.51 2870.54,2218.39 2870.54,2718.13 2881.14,2728.73 2881.14,2728.8 3013.32,2860.98 3374.64,2860.98 v1(3389.73,2845.89)
  Bottom Layer w25: v1(1192.2,2354.32) 1192.2,2534.04 1357.13,2698.97 R224.2@1357.13,2890.45
  other v1: 2478.05,2114.51
5V_EXT: C7.1 C156.1 C157.1 C158.1 J11.1 L11.2 L12.1 L13.1 R327.1 U27.1 U27.3 | length 1560.2
  Top Layer w20: U27.1@294.21,-640.91 292.4,-639.1 260.1,-639.1 240.8,-619.8 240.8,-578.55 253.24,-566.11 U27.3@294.21,-566.11
  Top Layer w25: U27.3@294.21,-566.11 296.03,-567.93 C7.1@349.65,-567.93 ; L12.1@431.7,-239.76 349.65,-321.81 C7.1@349.65,-567.93 ; J11.1@592.89,-759.47 532.75,-699.33 472.73,-699.33 430.68,-657.28 L13.1@430.68,-583.66 365.39,-583.66 C7.1@349.65,-567.93
  Layer 2 w6: v1(107.37,-546.72) 268.27,-707.62 541.04,-707.62 J11.1@592.89,-759.47
  Bottom Layer w6: R327.1@131.87,-546.72 145.14,-546.72 R327.1@147.11,-548.68
  Bottom Layer w25: v1(107.37,-546.72) R327.1@131.87,-546.72
5V_ISO: C4.1 C5.1 C17.1 C18.1 C61.1 C62.1 C130.1 R187.2 R265.2 U1.11 U1.16 U4.11 U4.16 U6.16 U26.1 U26.3 | length 3542.4
  Top Layer w25: R265.2@363.33,2637.65 365.46,2635.53 C130.1@365.46,2528.95 371.02,2523.39 v2(371.02,2469.46) ; v1(486.97,1416.31) 536.14,1416.31 C4.1@541.45,1421.63 U1.16@644.56,1421.63 ; v1(486.97,1691.91) 539.4,1691.91 C5.1@541.45,1693.95 541.45,1692.97 547.65,1686.77 568.45,1686.77 583.59,1671.63 U1.11@644.56,1671.63 ; v1(486.97,1947.81) 547.02,1947.81 C17.1@551.29,1952.08 U4.16@644.56,1952.08 ; v1(486.97,2223.4) C18.1@551.29,2223.4 ; v1(506.65,255.68) R187.2@565.71,255.68 ; C62.1@506.65,865.13 507.76,864.03 v1(507.76,818.8) ; C62.1@509.95,868.66 C61.1@572.94,868.66 572.94,869.64 579.14,875.84 609.94,875.84 625.26,891.17 U6.16@644.56,891.17 ; C18.1@551.29,2219.6 568.81,2202.08 U4.11@644.56,2202.08
  Layer 1 w25: v2(371.02,2469.46) 371.02,2339.35 v1(486.97,2223.4) v1(486.97,1947.81) v1(486.97,1691.91) v1(486.97,1416.31) 486.97,839.59 v1(507.76,818.8)
  Bottom Layer w25: U26.3@435.89,812.9 v1@501.85,812.9 ; U26.1@435.89,887.7 487.96,887.7 509.95,865.71 ; v1(506.65,255.68) 506.65,867.7
24V_EXT: J5.1 R315.1 | length 80.7
  Bottom Layer w50: R315.1@159.73,-135.3 159.73,-203.98 J5.1@168.21,-212.46
485_RX_EN: R28.1 U31.28 | length 866.1
  Top Layer w8: v1(1386.05,1735.93) 1388.39,1735.93 1402.67,1750.2 U31.28@1468.37,1750.2
  Bottom Layer w8: v1(1191.45,1038.7) 1191.45,1187.4 1386.05,1382 v1(1386.05,1735.93)
485_TX_EN: R30.1 U31.27 | length 964.6
  Top Layer w10: R30.1@1157.55,1096.16 R30.1@1168.79,1096.16 v1(1220.9,1096.16) ; v1(1356.11,1772.81) 1357.96,1770.95 1364.81,1770.95 1365.87,1769.89 U31.27@1468.37,1769.89
  Bottom Layer w10: v1@1220.9,1099.62 1220.9,1192.81 1395.57,1367.48 1408.89,1380.8 1408.89,1745.39 1395.57,1758.71 1381.48,1772.81 v1(1356.11,1772.81)
485A: D49.1 D55.2 L9.2 P1.1 | length 639.7
  Top Layer w10: P1.1@98.53,1115.38 137.74,1154.58 L9.2@401.68,1154.58
  Bottom Layer w50: P1.1@98.53,1115.38 215.57,1115.38 250.2,1150 D49.1@261.69,1150 269.96,1158.27 D55.2@269.96,1289.37
485B: D49.2 D52.2 L8.2 P1.2 | length 624.3
  Top Layer w10: P1.2@98.53,1015.38 111.81,1015.38 136.01,991.17 L8.2@401.68,991.17
  Bottom Layer w50: P1.2@98.53,1019.56 100.98,1017.11 102.72,1017.11 106.19,1020.58 205.6,1020.58 250.2,975.98 D49.2@261.69,975.98 ; P1.2@98.53,1020.58 98.53,915.16 D52.2@113.79,899.9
